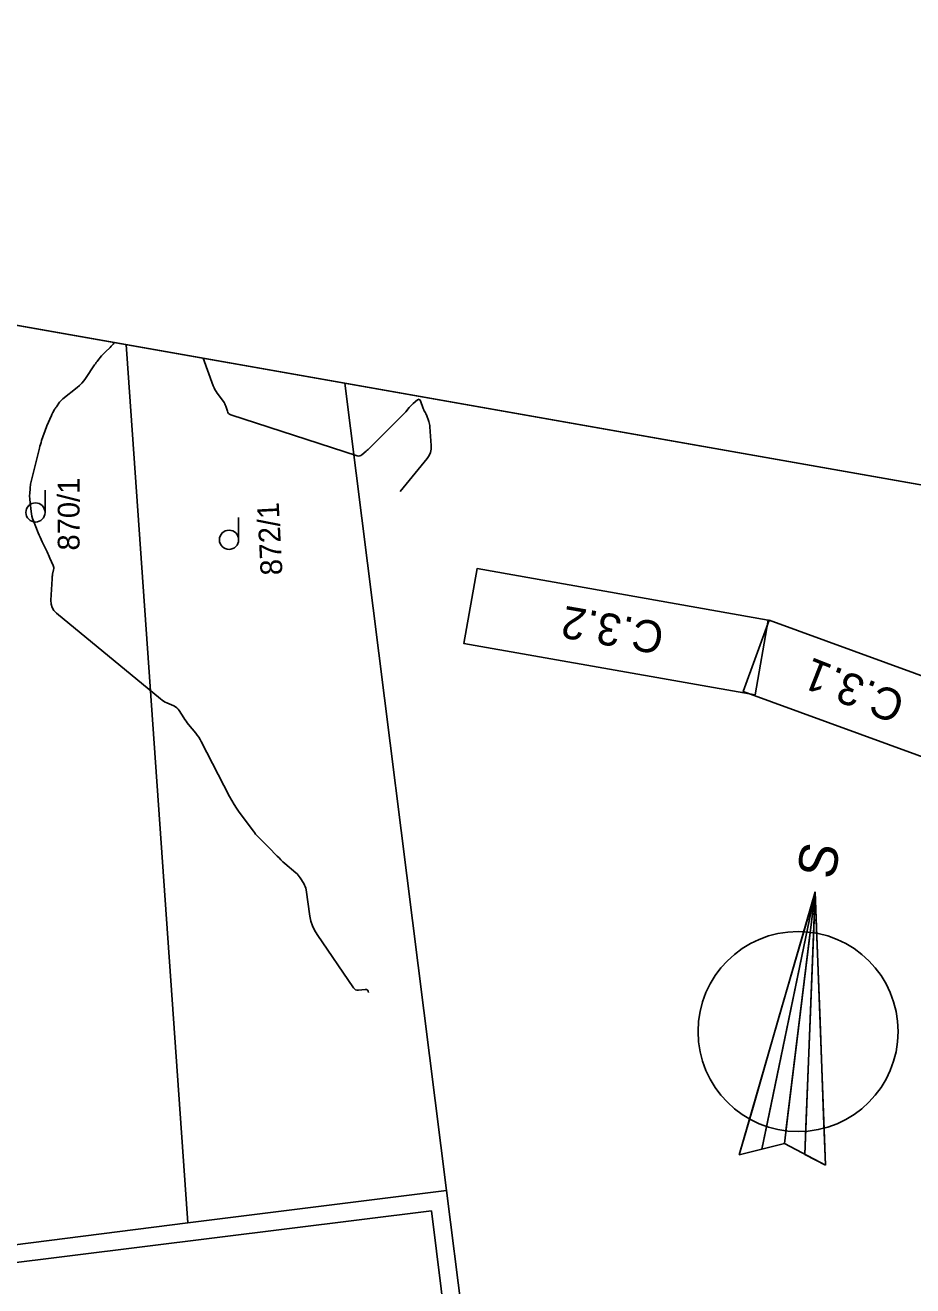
# Model space of a CAD drawing. Extents: x -534481 to -534262, y -1190577 to -1190138.
# Drawn here: x -534341.14 to -534306.48, y -1190186.88 to -1190137.67 of the extents above; entities that cross this region are included whole.
import ezdxf

# ---------------------------------------------------------------- set-up
doc = ezdxf.new("R2010")
doc.units = 0
for name, color, linetype in [('Definiční body', 7, 'Continuous'), ('Polygon budovy', 7, 'Continuous'), ('Polygon parcely', 7, 'Continuous'), ('Vrstva 18', 7, 'Continuous'), ('Vrstva 19', 7, 'Continuous'), ('Vrstva 30', 7, 'Continuous'), ('Vrstva 43', 7, 'Continuous'), ('Vrstva 44', 7, 'Continuous'), ('Vrstva 48', 7, 'Continuous')]:
    doc.layers.add(name, color=color, linetype=linetype)

msp = doc.modelspace()

# ---------------------------------------------------------------- linework, layer by layer
at = {"layer": 'Definiční body'}
for p, q in [((-534334.79, -1190184.43), (-534337.202, -1190150.142)), ((-534328.663, -1190151.648), (-534324.69, -1190183.16)), ((-534324.69, -1190183.16), (-534334.79, -1190184.43)), ((-534322.05, -1190204.13), (-534324.69, -1190183.16)), ((-534334.79, -1190184.43), (-534343.24, -1190185.5))]:
    msp.add_line(p, q, dxfattribs=at)
at = {"layer": 'Polygon parcely'}
msp.add_lwpolyline([(-534325.28, -1190183.96), (-534342.24, -1190186.06), (-534341.16, -1190195.04), (-534330.16, -1190193.66), (-534328.97, -1190203.08), (-534323, -1190202.33)], close=True, dxfattribs=at)
at = {"layer": 'Vrstva 18'}
msp.add_lwpolyline([(-534327.74, -1190175.432), (-534327.75, -1190175.377), (-534327.774, -1190175.339), (-534327.815, -1190175.319), (-534327.871, -1190175.317), (-534328.126, -1190175.342), (-534328.186, -1190175.341), (-534328.24, -1190175.325), (-534328.286, -1190175.295), (-534328.326, -1190175.249), (-534329.747, -1190173.168), (-534329.847, -1190173.002), (-534329.927, -1190172.828), (-534329.986, -1190172.647), (-534330.024, -1190172.457), (-534330.174, -1190171.425), (-534330.186, -1190171.361), (-534330.206, -1190171.299), (-534330.231, -1190171.239), (-534330.263, -1190171.182), (-534330.404, -1190170.957), (-534330.441, -1190170.902), (-534330.482, -1190170.851), (-534330.526, -1190170.803), (-534330.575, -1190170.758), (-534330.999, -1190170.397), (-534331.078, -1190170.328), (-534331.155, -1190170.257), (-534331.231, -1190170.183), (-534331.305, -1190170.108), (-534331.644, -1190169.755), (-534331.694, -1190169.704), (-534331.744, -1190169.653), (-534331.794, -1190169.602), (-534331.845, -1190169.552), (-534332.047, -1190169.351), (-534332.097, -1190169.3), (-534332.145, -1190169.247), (-534332.19, -1190169.192), (-534332.234, -1190169.136), (-534332.787, -1190168.388), (-534332.89, -1190168.243), (-534332.987, -1190168.093), (-534333.078, -1190167.94), (-534333.163, -1190167.783), (-534334.269, -1190165.639), (-534334.317, -1190165.552), (-534334.369, -1190165.467), (-534334.425, -1190165.386), (-534334.486, -1190165.307), (-534334.762, -1190164.968), (-534334.812, -1190164.906), (-534334.859, -1190164.842), (-534334.904, -1190164.776), (-534334.948, -1190164.71), (-534335.125, -1190164.429), (-534335.167, -1190164.371), (-534335.217, -1190164.321), (-534335.274, -1190164.279), (-534335.338, -1190164.245), (-534335.608, -1190164.126), (-534335.674, -1190164.094), (-534335.738, -1190164.057), (-534335.799, -1190164.017), (-534335.857, -1190163.972), (-534339.919, -1190160.626), (-534340.023, -1190160.521), (-534340.094, -1190160.401), (-534340.134, -1190160.268), (-534340.141, -1190160.12), (-534340.096, -1190159.281), (-534340.092, -1190159.237), (-534340.087, -1190159.193), (-534340.08, -1190159.149), (-534340.072, -1190159.105), (-534340.034, -1190158.931), (-534340.028, -1190158.888), (-534340.029, -1190158.846), (-534340.036, -1190158.804), (-534340.051, -1190158.763), (-534340.18, -1190158.476), (-534340.207, -1190158.415), (-534340.235, -1190158.354), (-534340.264, -1190158.293), (-534340.292, -1190158.232), (-534340.481, -1190157.837), (-534340.521, -1190157.75), (-534340.56, -1190157.663), (-534340.598, -1190157.576), (-534340.634, -1190157.488), (-534340.82, -1190157.024), (-534340.853, -1190156.933), (-534340.879, -1190156.841), (-534340.899, -1190156.748), (-534340.913, -1190156.653), (-534340.964, -1190156.187), (-534340.969, -1190156.132), (-534340.971, -1190156.078), (-534340.972, -1190156.023), (-534340.969, -1190155.968), (-534340.955, -1190155.749), (-534340.95, -1190155.695), (-534340.943, -1190155.641), (-534340.933, -1190155.587), (-534340.921, -1190155.534), (-534340.589, -1190154.183), (-534340.57, -1190154.11), (-534340.549, -1190154.036), (-534340.527, -1190153.964), (-534340.503, -1190153.891), (-534340.406, -1190153.603), (-534340.381, -1190153.531), (-534340.355, -1190153.46), (-534340.327, -1190153.389), (-534340.298, -1190153.319), (-534340.123, -1190152.904), (-534340.11, -1190152.875), (-534340.096, -1190152.845), (-534340.081, -1190152.817), (-534340.065, -1190152.789), (-534340, -1190152.677), (-534339.983, -1190152.649), (-534339.965, -1190152.622), (-534339.947, -1190152.595), (-534339.928, -1190152.569), (-534339.799, -1190152.393), (-534339.77, -1190152.356), (-534339.739, -1190152.321), (-534339.705, -1190152.288), (-534339.669, -1190152.258), (-534339.116, -1190151.819), (-534339.023, -1190151.739), (-534338.936, -1190151.652), (-534338.857, -1190151.559), (-534338.785, -1190151.46), (-534338.435, -1190150.938), (-534338.404, -1190150.891), (-534338.371, -1190150.846), (-534338.337, -1190150.801), (-534338.303, -1190150.757), (-534338.162, -1190150.583), (-534338.127, -1190150.54), (-534338.089, -1190150.498), (-534338.051, -1190150.458), (-534338.011, -1190150.419), (-534337.83, -1190150.25), (-534337.788, -1190150.208), (-534337.747, -1190150.165), (-534337.707, -1190150.12), (-534337.67, -1190150.073), (-534337.661, -1190150.061)], dxfattribs=at)
at = {"layer": 'Vrstva 19'}
msp.add_lwpolyline([(-534334.197, -1190150.672), (-534333.801, -1190151.749), (-534333.769, -1190151.826), (-534333.733, -1190151.9), (-534333.69, -1190151.972), (-534333.643, -1190152.041), (-534333.405, -1190152.36), (-534333.376, -1190152.403), (-534333.35, -1190152.448), (-534333.328, -1190152.495), (-534333.311, -1190152.544), (-534333.247, -1190152.744), (-534333.227, -1190152.79), (-534333.198, -1190152.828), (-534333.161, -1190152.857), (-534333.115, -1190152.877), (-534328.176, -1190154.481), (-534328.126, -1190154.491), (-534328.078, -1190154.488), (-534328.033, -1190154.473), (-534327.991, -1190154.444), (-534327.826, -1190154.304), (-534327.785, -1190154.268), (-534327.745, -1190154.232), (-534327.705, -1190154.195), (-534327.666, -1190154.157), (-534326.43, -1190152.921), (-534326.392, -1190152.882), (-534326.355, -1190152.843), (-534326.319, -1190152.803), (-534326.284, -1190152.762), (-534326.143, -1190152.597), (-534326.107, -1190152.557), (-534326.07, -1190152.518), (-534326.031, -1190152.48), (-534325.99, -1190152.445), (-534325.826, -1190152.304), (-534325.787, -1190152.28), (-534325.755, -1190152.277), (-534325.728, -1190152.295), (-534325.706, -1190152.336), (-534325.597, -1190152.639), (-534325.588, -1190152.66), (-534325.579, -1190152.682), (-534325.569, -1190152.702), (-534325.558, -1190152.723), (-534325.512, -1190152.804), (-534325.501, -1190152.824), (-534325.491, -1190152.845), (-534325.481, -1190152.867), (-534325.473, -1190152.888), (-534325.381, -1190153.143), (-534325.365, -1190153.193), (-534325.352, -1190153.244), (-534325.343, -1190153.295), (-534325.338, -1190153.348), (-534325.285, -1190154.085), (-534325.287, -1190154.222), (-534325.314, -1190154.35), (-534325.366, -1190154.471), (-534325.442, -1190154.584), (-534326.493, -1190155.876)], dxfattribs=at)
at = {"layer": 'Vrstva 30'}
msp.add_line((-534261.668, -1190163.461), (-534407.912, -1190137.674), dxfattribs=at)
msp.add_lwpolyline([(-534261.668, -1190163.461), (-534407.912, -1190137.674), (-534426.145, -1190241.079), (-534279.901, -1190266.866)], dxfattribs=at)
msp.add_lwpolyline([(-534312.634, -1190163.818), (-534324.009, -1190161.812), (-534323.493, -1190158.887), (-534312.119, -1190160.893)], close=True, dxfattribs=at)
at = {"layer": 'Vrstva 43'}
msp.add_line((-534261.668, -1190163.461), (-534407.912, -1190137.674), dxfattribs=at)
for points in [[(-534312.634, -1190163.818), (-534324.009, -1190161.812), (-534323.493, -1190158.887), (-534312.119, -1190160.893)], [(-534305.212, -1190166.563), (-534313.105, -1190163.69), (-534312.09, -1190160.899), (-534304.196, -1190163.772)]]:
    msp.add_lwpolyline(points, close=True, dxfattribs=at)
at = {"layer": 'Vrstva 44'}
for p, q in [((-534310.286, -1190171.498), (-534313.252, -1190181.766)), ((-534310.286, -1190171.498), (-534312.372, -1190181.548)), ((-534311.371, -1190180.337), (-534310.286, -1190171.498)), ((-534310.286, -1190171.498), (-534310.692, -1190181.754)), ((-534310.286, -1190171.498), (-534310.595, -1190172.568)), ((-534310.509, -1190172.575), (-534310.286, -1190171.498)), ((-534310.329, -1190172.597), (-534310.286, -1190171.498)), ((-534310.286, -1190171.498), (-534309.892, -1190182.179)), ((-534310.286, -1190171.498), (-534310.245, -1190172.611)), ((-534310.595, -1190172.568), (-534311.691, -1190176.363)), ((-534311.306, -1190176.411), (-534310.509, -1190172.575)), ((-534311.432, -1190180.833), (-534310.48, -1190173.082)), ((-534310.484, -1190176.512), (-534310.329, -1190172.597)), ((-534310.245, -1190172.611), (-534310.099, -1190176.559)), ((-534311.691, -1190176.363), (-534312.717, -1190179.915)), ((-534312.088, -1190180.179), (-534311.306, -1190176.411)), ((-534310.637, -1190180.358), (-534310.484, -1190176.512)), ((-534310.099, -1190176.559), (-534309.963, -1190180.253)), ((-534312.717, -1190179.915), (-534313.252, -1190181.766)), ((-534312.372, -1190181.548), (-534312.088, -1190180.179)), ((-534310.692, -1190181.754), (-534310.637, -1190180.358)), ((-534309.963, -1190180.253), (-534309.892, -1190182.179)), ((-534313.252, -1190181.766), (-534312.372, -1190181.548)), ((-534309.892, -1190182.179), (-534310.692, -1190181.754))]:
    msp.add_line(p, q, dxfattribs=at)
for points in [[(-534311.371, -1190180.337), (-534311.493, -1190181.33), (-534313.252, -1190181.766)], [(-534311.371, -1190180.337), (-534311.493, -1190181.33), (-534309.892, -1190182.179)]]:
    msp.add_lwpolyline(points, dxfattribs=at)
msp.add_circle((-534310.956, -1190176.957), 3.905, dxfattribs=at)
for start, end in [(84.3308, 85.5874), (84.3308, 85.5874), (80.4126, 81.6692), (80.4126, 81.6692)]:
    msp.add_arc((-534310.895, -1190176.461), 3.905, start, end, dxfattribs=at)
at = {"layer": 'Vrstva 48'}
for p, q in [((-534340.369, -1190156.694), (-534340.369, -1190155.819)), ((-534332.807, -1190157.76), (-534332.807, -1190156.885))]:
    msp.add_line(p, q, dxfattribs=at)
for centre in [(-534340.744, -1190156.694), (-534333.182, -1190157.76)]:
    msp.add_circle(centre, 0.375, dxfattribs=at)

# ---------------------------------------------------------------- texts
at = {"layer": 'Polygon budovy'}
for s, rotation, p in [('870/1', 90, (-534339.022, -1190158.18)), ('872/1', 93, (-534331.094, -1190159.126))]:
    msp.add_text(s, height=0.85, rotation=rotation, dxfattribs=at).set_placement(p)
at = {"layer": 'Vrstva 44'}
for s, height, rotation, p in [('C.3.2', 1.25, 170.1465, (-534316.129, -1190161.015)), ('C.3.1', 1.25, 158.5042, (-534306.696, -1190163.805)), ('S', 1.5, 80, (-534309.54, -1190171.06))]:
    msp.add_text(s, height=height, rotation=rotation, dxfattribs=at).set_placement(p)

doc.saveas('drawing.dxf')
